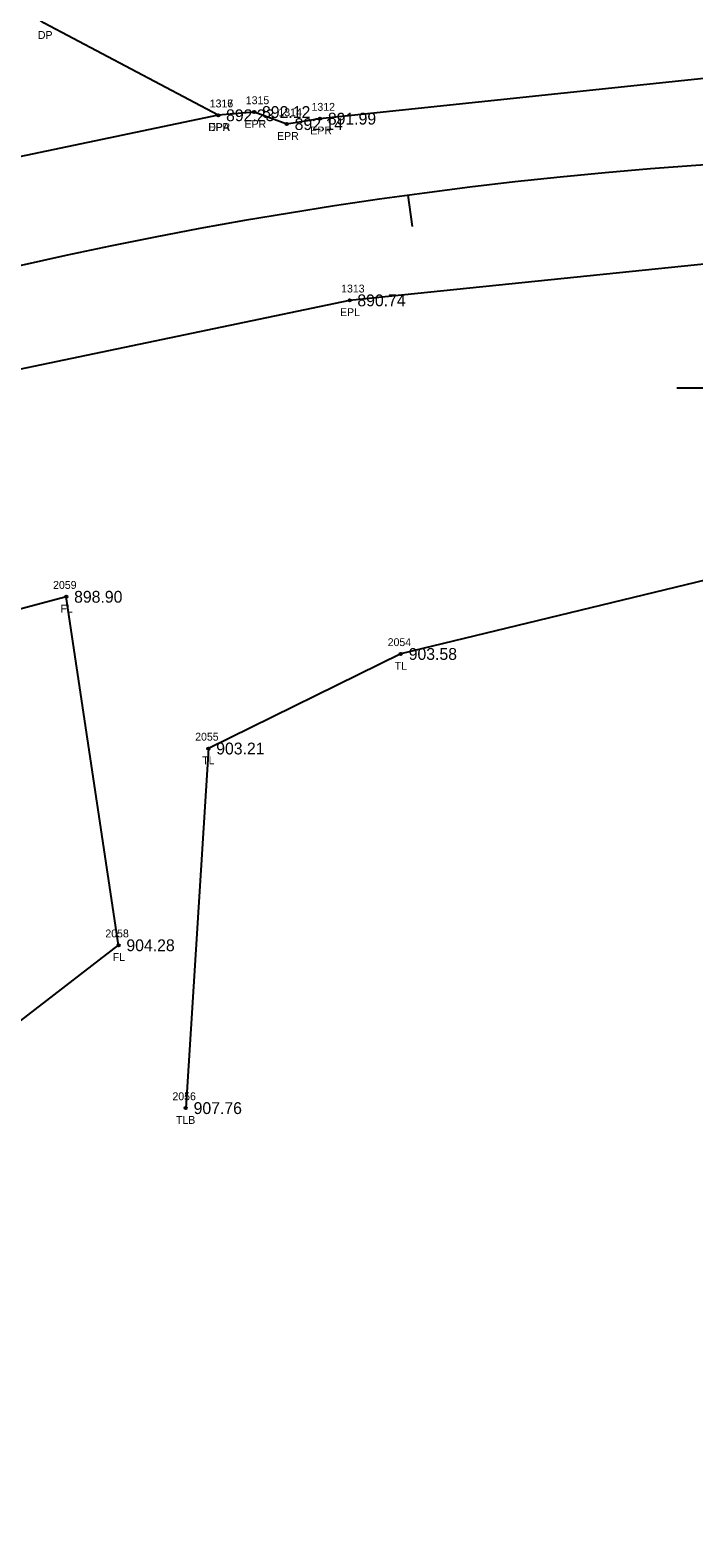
# Model space of a CAD drawing. Extents: x 1448136 to 1453623, y 1125056 to 1128842.
# Drawn here: x 1448999.1 to 1449083.5, y 1126756.9 to 1126948.2 of the extents above; entities that cross this region are included whole.
import ezdxf

# ---------------------------------------------------------------- set-up
doc = ezdxf.new("R2010")
doc.units = 0
for name, color, linetype in [('RD_EX_Driveway', 7, 'Continuous'), ('RD_EX_Driveway_txCode', 7, 'Continuous'), ('RD_EX_Fence_Other', 7, 'Continuous'), ('RD_EX_Fence_Other_txCode', 7, 'Continuous'), ('RD_EX_Road', 7, 'Continuous'), ('RD_EX_Road_txCode', 7, 'Continuous'), ('RD_EX_TX_Driveway_ELEV', 7, 'Continuous'), ('RD_EX_TX_Fence_Other_ELEV', 7, 'Continuous'), ('RD_EX_TX_Road_ELEV', 7, 'Continuous'), ('RD_EX_TX_VEG_ELEV', 7, 'Continuous'), ('RD_EX_UT', 7, 'Continuous'), ('RD_EX_VEG', 7, 'Continuous'), ('RD_EX_VEG_txCode', 7, 'Continuous'), ('RD_HC_Cl', 7, 'Continuous'), ('RD_HC_Data_Tic', 7, 'Continuous'), ('RD_SMD_Locator', 7, 'Continuous')]:
    doc.layers.add(name, color=color, linetype=linetype)

msp = doc.modelspace()

# ---------------------------------------------------------------- linework, layer by layer
at = {"layer": 'RD_EX_Driveway'}
msp.add_lwpolyline([(1449023.03, 1126937.4), (1449000.91, 1126949.09), (1448977.52, 1126965.39), (1448969.14, 1126957.73), (1448974.48, 1126944.7), (1448974.63, 1126933.49), (1448974.11, 1126927.16)], dxfattribs=at)
at = {"layer": 'RD_EX_Fence_Other'}
msp.add_lwpolyline([(1448975.76, 1126805.4), (1449010.37, 1126832.06), (1449003.73, 1126876.29), (1448947.02, 1126861.17), (1448899.19, 1126847.35), (1448908.83, 1126812.34)], dxfattribs=at)
at = {"layer": 'RD_EX_Road'}
for points in [[(1449482.54, 1126860.68), (1449432.31, 1126877.02), (1449388.08, 1126891.1), (1449338.36, 1126907.04), (1449288.58, 1126921), (1449240.68, 1126932.6), (1449188.86, 1126940.12), (1449140.06, 1126943.48), (1449087.15, 1126942.31), (1449035.96, 1126936.97), (1449031.74, 1126936.28), (1449027.6, 1126937.81), (1449023.03, 1126937.4), (1448974.11, 1126927.16), (1448972.81, 1126925.93), (1448941.11, 1126916.24), (1448934.6, 1126912.22), (1448888.05, 1126895.64)], [(1449474.36, 1126838.35), (1449426.72, 1126853.6), (1449379.49, 1126868.74), (1449332.07, 1126883.87), (1449284.48, 1126897.19), (1449236.53, 1126909.1), (1449187.55, 1126916.77), (1449138.32, 1126919.77), (1449088.85, 1126918.94), (1449039.71, 1126913.91), (1448991.01, 1126903.73), (1448942.83, 1126890.02), (1448896.24, 1126874.12)]]:
    msp.add_lwpolyline(points, dxfattribs=at)
at = {"layer": 'RD_EX_UT'}
msp.add_line((1449081.28, 1126902.82), (1449084.75, 1126902.82), dxfattribs=at)
at = {"layer": 'RD_EX_VEG'}
msp.add_lwpolyline([(1449580.16, 1126756.85), (1449515.49, 1126772.44), (1449452.16, 1126796.48), (1449411.7, 1126813.35), (1449361.89, 1126826.23), (1449322.6, 1126840.71), (1449267.19, 1126862.08), (1449183.91, 1126901.45), (1449150.59, 1126885.87), (1449094.51, 1126880.74), (1449046.23, 1126869.03), (1449021.78, 1126857.03), (1449018.91, 1126811.39)], dxfattribs=at)
at = {"layer": 'RD_HC_Cl'}
msp.add_arc((1449124.53, 1126359.54), 572.96, 72.66042, 109.74133, dxfattribs=at)
at = {"layer": 'RD_HC_Data_Tic'}
msp.add_line((1449047.13, 1126927.25), (1449047.67, 1126923.29), dxfattribs=at)
at = {"layer": 'RD_SMD_Locator'}
for centre in [(1449023.03, 1126937.4), (1449023.03, 1126937.4), (1449027.6, 1126937.81), (1449031.74, 1126936.28), (1449035.96, 1126936.97), (1449039.71, 1126913.91), (1449003.73, 1126876.29), (1449046.23, 1126869.03), (1449021.78, 1126857.03), (1449010.37, 1126832.06), (1449018.91, 1126811.39)]:
    msp.add_circle(centre, 0.15, dxfattribs=at)

# ---------------------------------------------------------------- texts
at = {"layer": 'RD_EX_Driveway_txCode'}
for s, p in [('DP', (1449000.13, 1126947.09)), ('1317', (1449021.97, 1126938.4)), ('DPA', (1449021.77, 1126935.4))]:
    msp.add_text(s, height=1, dxfattribs=at).set_placement(p)
at = {"layer": 'RD_EX_Fence_Other_txCode'}
for s, p in [('2059', (1449002.06, 1126877.29)), ('FL', (1449003, 1126874.29)), ('2058', (1449008.7, 1126833.06)), ('FL', (1449009.64, 1126830.06))]:
    msp.add_text(s, height=1, dxfattribs=at).set_placement(p)
at = {"layer": 'RD_EX_Road_txCode'}
for s, p in [('1316', (1449021.95, 1126938.4)), ('1315', (1449026.54, 1126938.81)), ('1314', (1449030.68, 1126937.28)), ('1312', (1449034.89, 1126937.97)), ('EPR', (1449021.8, 1126935.4)), ('EPR', (1449026.38, 1126935.81)), ('EPR', (1449030.51, 1126934.28)), ('EPR', (1449034.73, 1126934.97)), ('1313', (1449038.65, 1126914.91)), ('EPL', (1449038.51, 1126911.91))]:
    msp.add_text(s, height=1, dxfattribs=at).set_placement(p)
at = {"layer": 'RD_EX_TX_Driveway_ELEV'}
msp.add_text('892.23', height=1.5, dxfattribs=at).set_placement((1449024.03, 1126936.65))
at = {"layer": 'RD_EX_TX_Fence_Other_ELEV'}
for s, p in [('898.90', (1449004.73, 1126875.54)), ('904.28', (1449011.37, 1126831.31))]:
    msp.add_text(s, height=1.5, dxfattribs=at).set_placement(p)
at = {"layer": 'RD_EX_TX_Road_ELEV'}
for s, p in [('892.23', (1449024.03, 1126936.65)), ('892.12', (1449028.6, 1126937.06)), ('892.14', (1449032.74, 1126935.53)), ('891.99', (1449036.96, 1126936.22)), ('890.74', (1449040.71, 1126913.16))]:
    msp.add_text(s, height=1.5, dxfattribs=at).set_placement(p)
at = {"layer": 'RD_EX_TX_VEG_ELEV'}
for s, p in [('903.58', (1449047.23, 1126868.28)), ('903.21', (1449022.78, 1126856.28)), ('907.76', (1449019.91, 1126810.64))]:
    msp.add_text(s, height=1.5, dxfattribs=at).set_placement(p)
at = {"layer": 'RD_EX_VEG_txCode'}
for s, p in [('2054', (1449044.56, 1126870.03)), ('TL', (1449045.46, 1126867.03)), ('2055', (1449020.11, 1126858.03)), ('TL', (1449021, 1126855.03)), ('2056', (1449017.22, 1126812.39)), ('TLB', (1449017.67, 1126809.39))]:
    msp.add_text(s, height=1, dxfattribs=at).set_placement(p)

doc.saveas('drawing.dxf')
